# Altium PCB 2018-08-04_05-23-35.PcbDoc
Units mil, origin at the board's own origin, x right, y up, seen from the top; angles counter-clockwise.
Board outline 3500 x 5100 mil, 4 copper layers (Top Layer, MidLayer1, MidLayer2, Bottom Layer); 39 components, 19 nets, 107 pads, 114 vias.
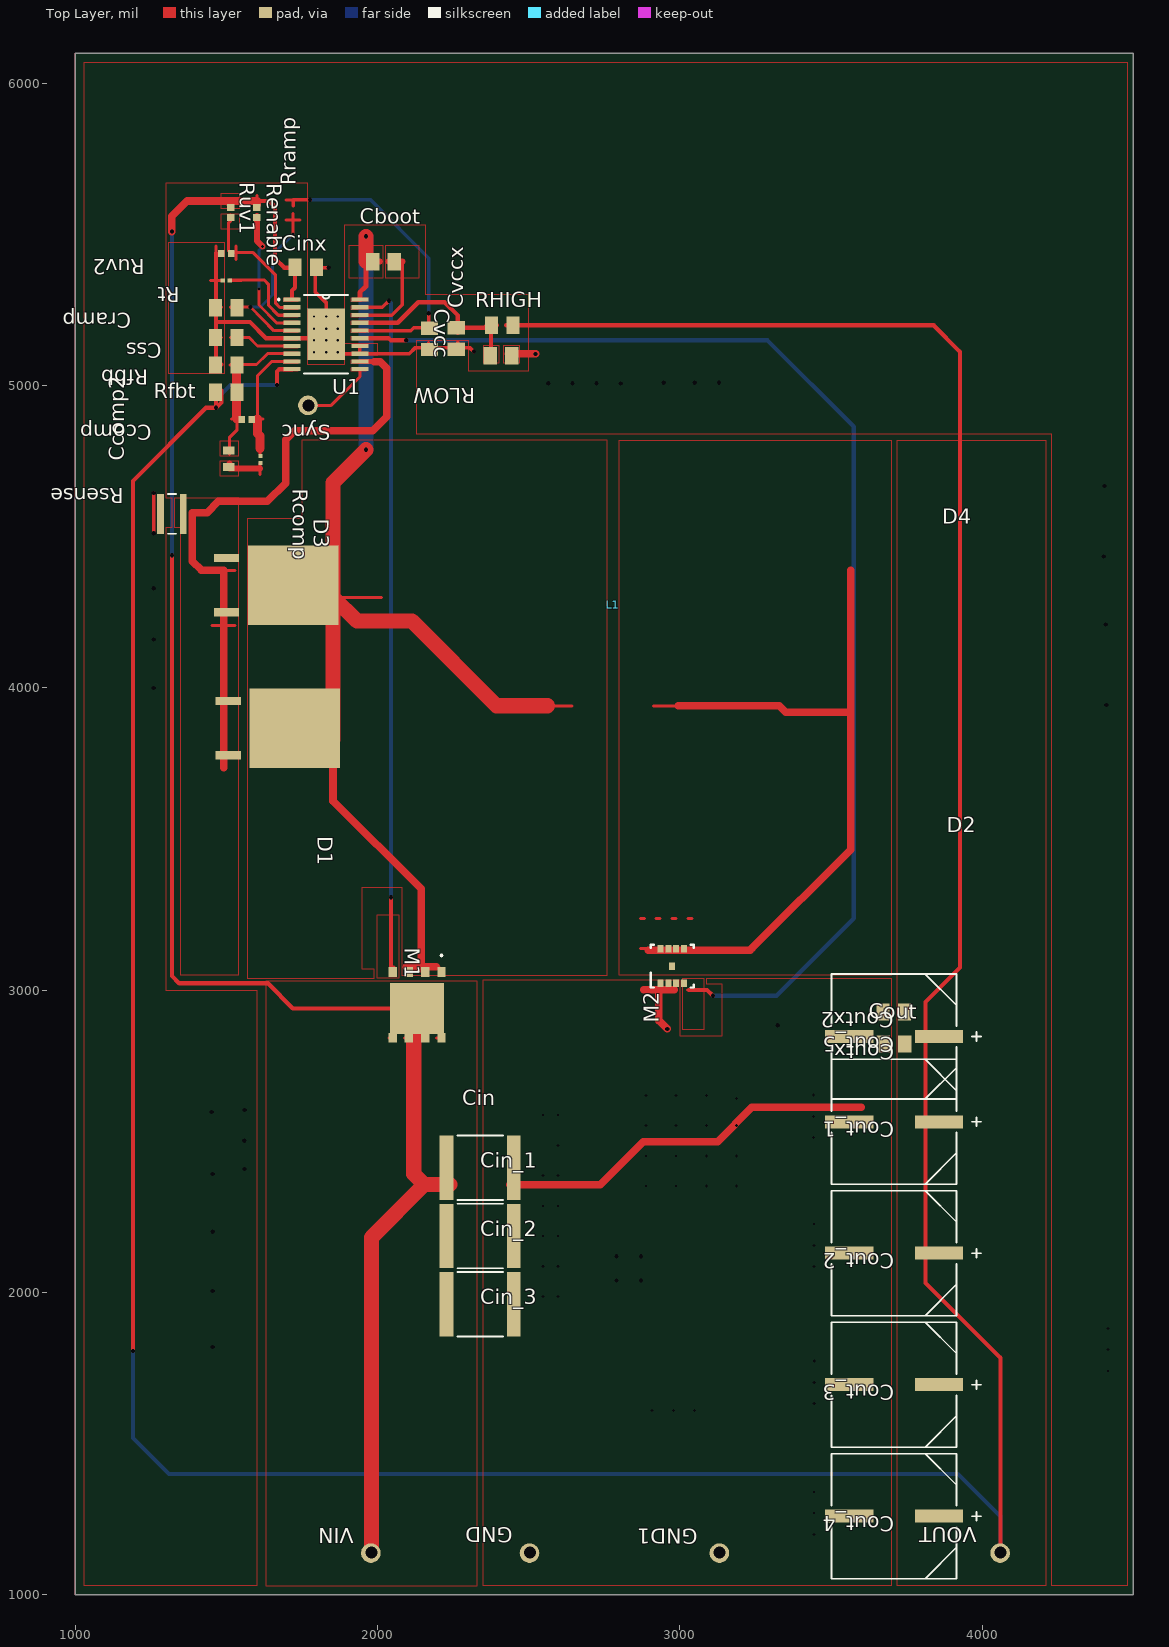
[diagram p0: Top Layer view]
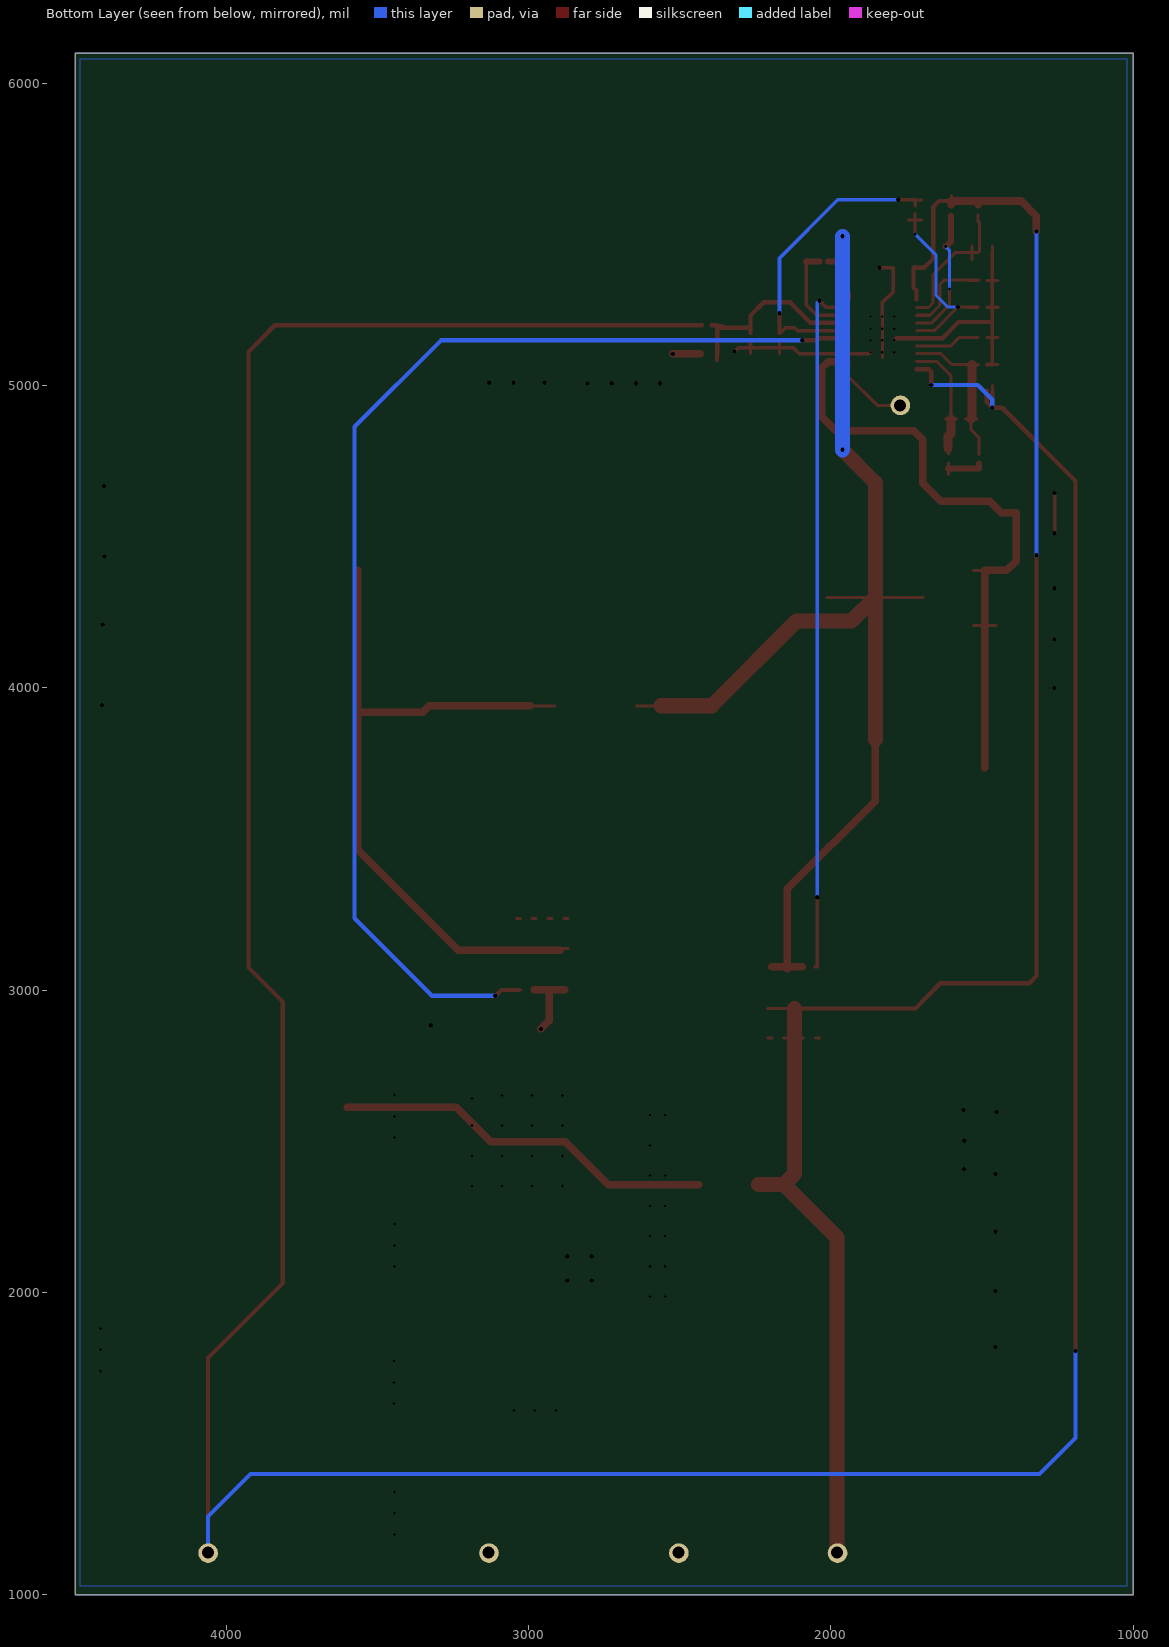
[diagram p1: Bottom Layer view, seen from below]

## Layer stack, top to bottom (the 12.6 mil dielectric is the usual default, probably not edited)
Top Layer: signal copper 1.4
Dielectric: core 12.6, FR-4, Dk 4.8
MidLayer1: signal copper 1.4
Dielectric: prepreg 12.6, FR-4, Dk 4.8
MidLayer2: signal copper 1.4
Dielectric: core 12.6, FR-4, Dk 4.8
Bottom Layer: signal copper 1.4

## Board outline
1000,1000 4500,1000 4500,6100 1000,6100

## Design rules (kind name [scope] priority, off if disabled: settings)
PlaneConnect [All] p0: scope1count=1 scope1_0_kind=Board scope1_0_value=Board scope2count=1 scope2_0_kind=Board scope2_0_value=Board commentlength=0 planeconnectstyle=Direct reliefexpansion=20 reliefentries=4 reliefconductorwidth=10 reliefairgap=10
PlaneConnect [All] p1: planeconnectstyle=Direct reliefexpansion=20 reliefentries=4 reliefconductorwidth=10 reliefairgap=10
PolygonConnect [All] p0: scope1count=1 scope1_0_kind=Board scope1_0_value=Board scope2count=1 scope2_0_kind=Board scope2_0_value=Board commentlength=0 connectstyle=Direct reliefconductorwidth=10 reliefentries=4 polygonreliefangle="90 Angle"
PolygonConnect [All] p1: connectstyle=Direct reliefconductorwidth=10 reliefentries=4 polygonreliefangle="90 Angle"

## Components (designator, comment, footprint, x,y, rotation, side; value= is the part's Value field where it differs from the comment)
Cboot "" 0805 2020,5410 r0 top
Ccomp "" 0402 1568,4888 r180 top
Ccomp2 "" 0603 1508,4758 r90 top
Cin_1 "" 2220_250 2340,2413 r0 top
Cin_2 "" 2220_250 2340,2187 r0 top
Cin_3 "" 2220_250 2340,1961 r0 top
Cinx "" 0805 1763,5392 r0 top
Cout_1 "" SM_RADIAL_10BMM 3709,2565 r180 top
Cout_2 "" SM_RADIAL_10BMM 3709,2130 r180 top
Cout_3 "" SM_RADIAL_10BMM 3709,1695 r180 top
Cout_4 "" SM_RADIAL_10BMM 3709,1260 r180 top
Cout_5 "" SM_RADIAL_10BMM 3709,2847 r180 top
Coutx "" 0805 3709,2822 r180 top
Coutx2 "" 0805 3708,2928 r180 top
Cramp "" 0805 1500,5258 r180 top
Css "" 0805 1500,5159 r180 top
Cvcc "" 0805 2172,5155 r270 top
Cvccx "" 0805 2261,5156 r90 top
D1 "" DPAK 1721,3867 r270 top
D3 "" DPAK 1715,4340 r270 top
GND "" TP-1502#1 2503,1138 r180 top
GND1 "" TP-1502#2 3131,1138 r180 top
L1 "" SER2915L 2779,4275 r180 top
M1 "" TRANS_NexFET_Q5A 2131,2952 r270 top
M2 "" DQG0008A 2975,3080 r90 top
Rcomp "" 0201 1613,4756 r270 top
Renable "" 0402 1601,5573 r270 top
Rfbb "" 0805 1500,5068 r180 top
Rfbt "" 0805 1500,4978 r0 top
RHIGH "" 0805 2413,5200 r0 top
RLOW "" 0805 2409,5099 r180 top
Rsense "" 0612 1320,4576 r180 top
Rt "" 0201 1500,5348 r180 top
Ruv1 "" 0402 1515,5573 r270 top
Ruv2 "" 0402 1500,5437 r180 top
Sync "" TP-1502#1 1770,4935 r180 top
U1 "" MXA20A 1830,5170 r0 top
VIN "" TP-1502#1 1978,1138 r180 top
VOUT "" TP-1502#1 4060,1138 r180 top

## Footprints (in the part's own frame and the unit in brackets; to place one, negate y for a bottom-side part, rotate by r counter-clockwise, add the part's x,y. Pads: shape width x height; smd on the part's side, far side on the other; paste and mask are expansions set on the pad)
0201 [mil]
  rect 14x13 smd: 1(-11.5,0) 2(11.5,0)
0402 [mil]
  rect 22x24 smd: 1(-16.5,0) 2(16.5,0)
0603 [mil]
  rect 26x38 smd: 1(-27.5,0) 2(27.5,0)
0612 [mil]
  rect 22x132 smd: 1(-37.5,0) 2(37.5,0)
  silkscreen extent -13,-66 13,66
0805 [mil]
  rect 44x57 smd: 1(-35.5,0) 2(35.5,0)
2220_250 [mil]
  rect 45x213 smd: 1(-111.5,0) 2(111.5,0)
  silkscreen extent -76,-106 76,106
DPAK [mm]
  rect 0.701x2.111 smd: 1(-2.28,-5.45) 3(2.28,-5.45)
  rect 6.7x7.605 smd: 2(0,0.152)
DQG0008A [mm]
  rect 0.63x0.5 smd: 1(-1.435,0.975) 2(-1.435,0.325) 3(-1.435,-0.325) 4(-1.435,-0.975) 5(1.435,-0.975) 6(1.435,-0.325) 7(1.435,0.325) 8(1.435,0.975) 9(0,0)
  silkscreen extent -1.8,-1.8 1.8,1.8
MXA20A [mil]
  rect 56x14 smd: 1(-112,115.16) 2(-112,89.57) 3(-112,63.98) 4(-112,38.39) 5(-112,12.8) 6(-112,-12.8) 7(-112,-38.39) 8(-112,-63.98) 9(-112,-89.57) 10(-112,-115.16) 11(112,-115.16) 12(112,-89.57) 13(112,-63.98) 14(112,-38.39) 15(112,-12.8) 16(112,12.8) 17(112,38.39) 18(112,63.98) 19(112,89.57) 20(112,115.16)
  rect 124x171 smd: 21(0,0)
  silkscreen extent -160,-130 74,130
SER2915L [mil]
SM_RADIAL_10BMM [mil]
  rect 160x43 smd: 1(-148.5,0) 2(148.5,0)
  silkscreen extent -288,-207 207,207
TP-1502#1 [mil]
  round 65 / inner round 0 / far side round 65 hole 32: 1(0,0)
TP-1502#2 [mil]
  round 65 / inner round 0 / far side round 65 hole 32: 1(0,0) 1(0,0)
TRANS_NexFET_Q5A [mm]
  rect 0.8x0.7 smd: 1(-2.752,2.055) 2(-2.752,0.685) 3(-2.752,-0.685) 4(-2.752,-2.055) 5(2.752,-2.055) 6(2.752,-0.685) 7(2.752,0.685) 8(2.752,2.055)
  rect 4.3x4.56 smd: 9(0.3,0)
  silkscreen extent -4.22,1.98 -4.07,2.13

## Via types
v1: diameter 0, hole 10, Top Layer to Bottom Layer, 50 vias
v2: diameter 0, hole 14, Top Layer to Bottom Layer, 47 vias
v3: diameter 0, hole 8, Top Layer to Bottom Layer, 12 vias
v4: diameter 0, hole 40, Top Layer to Bottom Layer, 5 vias

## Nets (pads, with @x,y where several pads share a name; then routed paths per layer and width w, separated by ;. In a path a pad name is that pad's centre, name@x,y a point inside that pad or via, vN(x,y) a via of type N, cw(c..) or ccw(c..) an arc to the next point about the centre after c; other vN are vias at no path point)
0: Cin_1.2 Cin_2.2 Cin_3.2 Cinx.2 Cout_1.2 Cout_2.2 Cout_3.2 Cout_4.2 Cout_5.2 Coutx2.2 Coutx.2 Cramp.2 Css.2 Cvcc.2 Cvccx.1 GND1.1 GND.1 M2.1 M2.2 M2.3 Rfbb.2 RLOW.1 Rsense.2 Rt.2 Ruv2.2 U1.6 U1.13 U1.14 U1.21 | length 3640.4
  Top Layer w10: Rfbb.2@1447,5069.5 Rfbb.2@1484,5069.5 ; Css.2@1447,5159.5 Css.2@1484,5159.5 ; Cramp.2@1447,5259.5 Cramp.2@1484,5259.5 ; 1447,5348.5 Rt.2@1484,5348.5 ; 1465.5,5417 1465.5,5462 ; U1.21@1829,5094 U1.21@1829,5245 ; Cvcc.2@2169.5,5106 2169.5,5143 ; Cvccx.1@2265.5,5106 2265.5,5143 ; 2875,3001.5 2886,3001.5 ; 2925,3001.5 2936,3001.5 ; 2975,3001.5 2986,3001.5
  Top Layer w12: v2(1260,4512) 1260,4580 v2(1260,4645) ; Css.2@1466,5155 1466,5070 Rfbb.2@1484,5070 ; Css.2@1466,5160 1466,5260 1466,5349 1466,5440 ; U1.21@1783,5157 v3(1790,5150) ; v3(1830,5229) 1830,5275 1794,5310 1794,5390 v2(1839,5390) ; v3(1869,5110) 1874,5106 U1.13 ; U1.14@1942,5131 U1.13 ; 2266,5144 Cvccx.1@2266,5125 ; v2(2319,5113) 2306,5125 Cvccx.1@2266,5125 ; U1.13 2105,5106 2124,5125 2170,5125 Cvccx.1@2266,5125
  Top Layer w14: 1472,5211 1578,5211 1631,5157 1717,5157 U1.21@1783,5157
  Top Layer w25: RLOW.1@2432,5105 2444,5105 v2(2523,5105) ; Cin_1.2@2437,2357 2737,2357 2879,2499 3125,2499 3239,2613 3600,2613 ; 2881,3001 2931,3001 ; v2(2959,2872) 2931,2900 2931,3001 ; 2981,3001 2931,3001
  other v1: 3444,1200 3444,1270 3444,1340 2909,1609 2979,1609 3049,1609 3445,1633 3445,1703 4416,1741 3445,1773 4416,1811 4416,1881 2548,1987 2598,1987 3444,2086 2548,2087 2598,2087 3444,2156 2548,2187 2598,2187 3444,2226 2548,2287 2598,2287 2888,2352 2988,2352 3088,2352 3188,2352 2548,2387 2598,2387 2888,2452 2988,2452 3088,2452 3188,2452 2598,2487 3443,2513 2888,2552 2988,2552 3088,2552 3188,2552 3443,2583 2548,2587 2598,2587 3188,2642 2888,2652 2988,2652 3088,2652 3443,2653
  other v2: 1455,1820 1455,2005 2791,2040 2872,2040 2791,2120 2872,2120 1455,2201 1455,2392 1560,2409 1559,2502 1452,2597 1561,2604 3324,2884 4411,3944 1260,4000 1260,4160 4409,4210 1260,4330 4403,4435 4405,4668 2805,5007 2565,5008 2645,5008 2725,5008 2947,5010 3050,5010 3130,5010
  other v3: 1790,5110 1830,5110 1830,5150 1869,5150 1790,5189 1830,5189 1869,5189 1790,5229 1869,5229
  other v4: 2504,1140 3132,1140
1: Ruv1.2 Ruv2.1 U1.2 | length 507
  Top Layer w10: Ruv1.2@1513,5565 1513,5544 1508,5539 1508,5446 1514,5440 1533,5440 1589,5440 1662,5367 1662,5274 1677,5259 U1.2@1717,5259 ; 1532.5,5417 1532.5,5462
2: Rt.1 U1.3 | length 332.8
  Top Layer w10: Rt.1@1510,5349 1533,5349 1626,5349 1639,5336 1639,5267 1672,5233 U1.3@1717,5233 ; Rt.1@1514,5348.5 1551,5348.5
3: Renable.2 U1.4 | length 477.2
  Top Layer w10: 1601.5,5525 Renable.2@1601.5,5562 ; v1(1608,5320) 1608,5267 1666,5208 U1.4@1717,5208
  Top Layer w20: Renable.2@1602,5561 1602,5544 1602,5478 v1(1620,5460)
  Bottom Layer w10: v1(1608,5320) 1608,5448 v1(1620,5460)
4: Cramp.1 U1.5 | length 698.3
  Top Layer w10: Cramp.1@1514,5259.5 Cramp.1@1551,5259.5 ; Cramp.1@1520,5260 1533,5260 v2(1580,5260) 1657,5182 U1.5@1717,5182 ; 1698,5547.5 1743,5547.5 ; v1(1721,5501) 1721,5548 1721,5569
  Bottom Layer w10: v2(1580,5260) 1613,5260 1653,5300 1653,5433 v1(1721,5501)
5: Css.1 U1.7 | length 248.3
  Top Layer w10: Css.1@1514,5159.5 Css.1@1551,5159.5 ; Css.1@1518,5160 1533,5160 1575,5160 1603,5131 U1.7@1717,5131
6: Cout_1.1 Cout_2.1 Cout_3.1 Cout_4.1 Cout_5.1 Coutx2.1 Coutx.1 Cvccx.2 Rfbt.1 RHIGH.1 RHIGH.2 RLOW.2 U1.10 U1.17 VOUT.1 | length 13592.6
  Top Layer w10: Rfbt.1@1465.5,4956 Rfbt.1@1465.5,5001 ; Cvccx.2@2265.5,5173 Cvccx.2@2265.5,5210 ; RHIGH.1@2357,5199.5 RHIGH.1@2394,5199.5 ; 2424,5199.5 RHIGH.2@2461,5199.5
  Top Layer w14: v2(1191,1807) 1191,4685 1433,4927 v2(1466,4927) ; Rfbt.1@1466,4979 v2(1466,4927) ; Rfbt.1@1484,4984 1484,4944 v2(1466,4927) ; v2(1668,5002) 1668,5047 1675,5054 U1.10@1717,5054 ; U1.17@1942,5208 2067,5208 2135,5276 2222,5276 2266,5232 Cvccx.2@2266,5192 ; Cvccx.2@2266,5174 Cvccx.2@2266,5192 ; RLOW.2@2377,5085 2377,5105 2376,5106 RHIGH.1@2376,5200 ; RHIGH.1@2395,5200 RHIGH.1@2376,5200 ; 2426,5200 2443,5200 3840,5200 3927,5112 3927,4300 3927,3830 3927,3075 3813,2961 3813,2032 4061,1784 v4(4061,1140) ; Cvccx.2@2266,5192 2369,5192 RHIGH.1@2376,5200
  Bottom Layer w14: v2(1191,1807) 1191,1519 1310,1400 3920,1400 4061,1259 v4(4061,1140) ; v2(1466,4927) 1466,4954 1514,5002 v2(1668,5002)
7: Cin_1.1 Cin_2.1 Cin_3.1 Cinx.1 M1.5 M1.6 M1.7 M1.8 M1.9 Renable.1 Ruv1.1 U1.1 VIN.1 | length 6344.9
  Top Layer w10: Renable.1@1601.5,5592 1601.5,5629 ; M1.5@2038,2841.5 M1.5@2051,2841.5 ; 2038,2939.5 M1.9@2209,2939.5 ; 2090,2841.5 M1.6@2103,2841.5 ; 2143,2841.5 M1.7@2156,2841.5 ; 2195,2841.5 M1.8@2208,2841.5
  Top Layer w14: v2(1320,4439) 1320,3047 1344,3023 1638,3023 1720,2940 M1.9@2120,2940 ; 1602,5611 1642,5611 1661,5592 1661,5421 1692,5390 1727,5390 1727,5324 1717,5315 U1.1@1717,5285
  Top Layer w25: v2(1320,5510) 1320,5560 1371,5611 1513,5611 ; Ruv1.1@1513,5598 1513,5611 ; Renable.1@1602,5598 1602,5611 1513,5611
  Top Layer w50: v4(1980,1140) 1980,2182 2155,2357 ; M1.9@2120,2940 2120,2392 2155,2357 ; Cin_1.1@2240,2357 2155,2357
  Bottom Layer w14: v2(1320,4439) v2(1320,5510)
8: Ccomp2.2 Ccomp.2 Rfbb.1 Rfbt.2 U1.8 | length 648.3
  Top Layer w10: Ccomp2.2@1510,4773 1510,4793 1510,4828 1536,4854 1536,4890 ; 1512,5069 1532,5069 1533,5070 1600,5070 1636,5106 U1.8@1717,5106 ; Rfbb.1@1514,5069.5 Rfbb.1@1551,5069.5 ; 1517,4889.5 Ccomp.2@1554,4889.5 ; Rfbt.2@1532.5,4956 Rfbt.2@1532.5,5001
  Top Layer w30: Rfbb.1@1533,5070 1533,4979 1533,4893 1536,4890
9: Ccomp.1 Rcomp.1 U1.9 | length 451.2
  Top Layer w10: Ccomp.1@1584,4889.5 1621,4889.5 ; 1603,4890 1603,5033 1650,5080 U1.9@1717,5080 ; Rcomp.1@1611.5,4774 1611.5,4811
  Top Layer w30: 1603,4890 1603,4842 1612,4833 1612,4793
10: M2.5 M2.6 M2.7 M2.8 M2.9 | length 2710.2
  Top Layer w10: 2870,3138.5 3041,3138.5 ; 2870,3237.5 2883,3237.5 ; 2913,3940.5 3076,3940.5 ; 2922,3237.5 2935,3237.5 ; 2975,3237.5 2988,3237.5 ; 3027,3237.5 3040,3237.5
  Top Layer w25: 2896,3133 3180,3133 3233,3133 3239,3139 3565,3465 3565,3736 3565,3905 ; 2995,3941 3329,3941 3350,3920 3565,3920 3565,3919 3565,3905 ; 3565,4389 3565,4206 3565,3905
11: Cboot.1 D1.2 D3.2 M1.1 M1.2 M1.3 U1.20 | length 4320.7
  Top Layer w10: D3.2@1693,4299.5 2013,4299.5 ; 2093,3077.5 2104,3077.5 ; 2143,3077.5 2154,3077.5 ; 2193,3077.5 2204,3077.5 ; 2480,3940.5 2643,3940.5
  Top Layer w16: U1.20@1942,5285 1942,5309 1962,5328 1962,5411
  Top Layer w20: 1962,5411 2009,5411
  Top Layer w25: D1.2@1853,3830 1853,3626 2145,3335 2145,3078 ; 2095,3078 2138,3078 ; M1.2@2145,3071 2145,3078 ; 2195,3078 2145,3078
  Top Layer w50: D1.2@1853,3830 D3.2@1853,4300 ; v2(1962,4788) 1853,4679 D3.2@1853,4300 ; 1962,5411 v2(1962,5494) ; 2562,3941 2394,3941 2114,4221 1932,4221 D3.2@1853,4300
  Bottom Layer w50: v2(1962,4788) v2(1962,5494)
12: D1.1 D1.3 D3.1 D3.3 Rsense.1 U1.12 | length 2197.3
  Top Layer w10: 1453,4206 1528,4206 ; 1453,4389 1528,4389
  Top Layer w15: U1.12@1942,5080 1990,5080
  Top Layer w25: 1491,3736 1491,3919 1491,4206 1491,4389 1418,4389 1387,4420 1387,4580 1437,4580 1474,4617 1636,4617 1696,4677 1696,4821 1726,4851 1984,4851 2031,4898 2031,5058 2009,5079 1990,5079
13: M2.4 U1.15 | length 4050.7
  Top Layer w10: 3025,3001.5 3036,3001.5
  Top Layer w14: U1.15@1942,5157 2037,5157 2045,5150 v2(2095,5150) ; 3031,3001 3090,3001 v2(3110,2982)
  Bottom Layer w14: v2(2095,5150) 3290,5150 3576,4864 3576,3238 3320,2982 v2(3110,2982)
14: Ccomp2.1 Rcomp.2 | length 155
  Top Layer w10: 1611.5,4707 Rcomp.2@1611.5,4744
  Top Layer w20: Ccomp2.1@1510,4742 1510,4726 1612,4726
15: Cvcc.1 U1.16 | length 1118.7
  Top Layer w10: 1698,5614.5 1743,5614.5 ; Cvcc.1@2169.5,5173 Cvcc.1@2169.5,5210
  Top Layer w12: 1721,5596 1721,5615 v2(1777,5615) ; U1.16@1942,5182 2110,5182 2120,5192 2150,5192 2170,5173 2170,5192 v2(2170,5240)
  Bottom Layer w12: v2(1777,5615) 1977,5615 2170,5422 v2(2170,5240)
16: M1.4 U1.19 | length 2322
  Top Layer w10: 2043,3077.5 2054,3077.5
  Top Layer w12: U1.19@1942,5259 2016,5259 v2(2038,5281) ; 2045,3078 v2(2045,3308)
  Bottom Layer w12: v2(2038,5281) 2045,5274 v2(2045,3308)
17: Cboot.2 U1.18 | length 342.5
  Top Layer w12: U1.18@1942,5233 2047,5233 2082,5268 2082,5411
  Top Layer w20: Cboot.2@2037,5411 2082,5411
19: Sync.1 U1.11 | length 233.4
  Top Layer w10: v4(1772,4935) 1847,4935 1942,5030 U1.11@1942,5054

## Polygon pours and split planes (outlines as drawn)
8 on Top Layer " " (solid, pour order 0): 1480,4767 1480,4818 1539,4818 1539,4767
14 on Top Layer " " (solid, pour order 1): 1480,4700 1480,4751 1539,4751 1539,4700
7 on Top Layer " " (solid, pour order 2): 1690,5278 1690,5291 1736,5291 1736,5278
1 on Top Layer " " (solid, pour order 3): 1690,5252 1690,5265 1736,5265 1736,5252
2 on Top Layer " " (solid, pour order 4): 1690,5227 1690,5240 1736,5240 1736,5227
3 on Top Layer " " (solid, pour order 5): 1690,5201 1690,5214 1736,5214 1736,5201
4 on Top Layer " " (solid, pour order 6): 1690,5175 1690,5188 1736,5188 1736,5175
5 on Top Layer " " (solid, pour order 7): 1690,5124 1690,5137 1736,5137 1736,5124
8 on Top Layer " " (solid, pour order 8): 1690,5099 1690,5112 1736,5112 1736,5099
9 on Top Layer " " (solid, pour order 9): 1690,5073 1690,5086 1736,5086 1736,5073
6 on Top Layer " " (solid, pour order 10): 1690,5047 1690,5060 1736,5060 1736,5047
11 on Top Layer " " (solid, pour order 11): 1914,5278 1914,5291 1961,5291 1961,5278
16 on Top Layer " " (solid, pour order 12): 1914,5252 1914,5265 1961,5265 1961,5252
17 on Top Layer " " (solid, pour order 13): 1914,5227 1914,5240 1961,5240 1961,5227
6 on Top Layer " " (solid, pour order 14): 1914,5201 1914,5214 1961,5214 1961,5201
15 on Top Layer " " (solid, pour order 15): 1914,5175 1914,5188 1961,5188 1961,5175
13 on Top Layer " " (solid, pour order 16): 1914,5150 1914,5163 1961,5163 1961,5150
12 on Top Layer " " (solid, pour order 17): 1914,5073 1914,5086 1961,5086 1961,5073
19 on Top Layer " " (solid, pour order 18): 1914,5047 1914,5060 1961,5060 1961,5047
17 on Top Layer " " (solid, pour order 19): 2027,5355 2027,5465 2137,5465 2137,5355
11 on Top Layer " " (solid, pour order 20): 1907,5355 1907,5465 2017,5465 2017,5355
6 on Top Layer " " (solid, pour order 21): 2351,5075 2351,5134 2402,5134 2402,5075
1 on Top Layer " " (solid, pour order 22): 1483,5518 1483,5569 1542,5569 1542,5518
7 on Top Layer " " (solid, pour order 23): 1483,5585 1483,5636 1542,5636 1542,5585
11 on Top Layer " " (solid, pour order 24): 2760,3050 2760,4820 1750,4820 1750,4560 1569,4560 1569,3040 1990,3040 1990,3070 1950,3070 1950,3340 2080,3340 2080,3050
6 on Top Layer " " (solid, pour order 25): 3720,4820 4210,4820 4210,1030 3720,1030
12 on Top Layer " " (solid, pour order 26): 1540,4630 1540,3050 1350,3050 1350,4530 1330,4530 1330,4630
13 on Top Layer " " (solid, pour order 27): 3010,3040 3080,3040 3080,2870 3010,2870
10 on Top Layer " " (solid, pour order 28): 3699,4820 3699,3050 2800,3050 2800,4820
16 on Top Layer " " (solid, pour order 29): 2000,3250 2070,3250 2070,3040 2000,3040
7 on Top Layer " " (solid, pour order 30): 2330,1030 2330,3030 1630,3030 1630,1030
0 on Top Layer " " (solid, pour order 31): 1690,5150 1690,5163 1736,5163 1736,5150
0 on Top Layer " " (solid, pour order 32): 1914,5099 1914,5112 1961,5112 1961,5099
0 on Top Layer " " (solid, pour order 33): 2418,5075 2418,5134 2469,5134 2469,5075
0 on Top Layer " " (solid, pour order 35): 2500,5300 2160,5300 2160,5530 1890,5530 1890,5140 2000,5140 2000,5100 1890,5100 1890,5070 1770,5070 1770,5670 1300,5670 1300,4630 1320,4630 1320,4530 1300,4530 1300,3000 1600,3000 1600,1030 1030,1030 1030,6070 4480,6070 4480,1030 4230,1030 4230,4840 2130,4840 2130,5150 2300,5150 2300,5050 2500,5050
0 on Top Layer " " (solid, pour order 36): 2350,3035 3000,3035 3000,2850 3140,2850 3140,3020 3090,3020 3090,3040 3700,3040 3700,1030 2350,1030
0 on Top Layer " " (solid, pour order 37): 1493,5474 1493,5039 1310,5039 1310,5370 1310,5391 1310,5474
0 on Bottom Layer " " (solid, pour order 34): 4485,6080 4485,1030 1020,1030 1020,6080

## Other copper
Multi-Layer:
  the board outline again, w1

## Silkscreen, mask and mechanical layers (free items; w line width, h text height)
Top Overlay:
  text "Rramp" at 1730,5663 h50 r90
  text "D4" at 3869,4543 h50
  text "D2" at 3883,3523 h50
  text "Cout" at 3625,2906 h50
  text "Cin" at 2280,2620 h50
